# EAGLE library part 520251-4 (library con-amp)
AMP connector
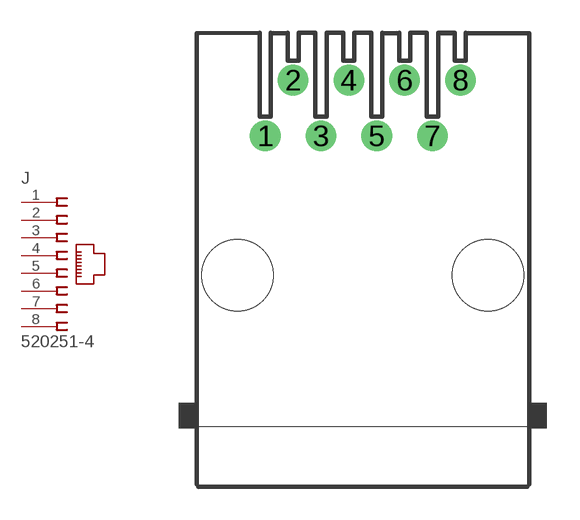
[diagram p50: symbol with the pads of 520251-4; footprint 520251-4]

Designator prefix J

## 520251-4 (MF: TYCO ELECTRONICS; MPN: 5520251-4; OC_FARNELL: 1557070; OC_NEWARK: 42K7223)  [520251-4]
1  1  pas
2  2  pas
3  3  pas
4  4  pas
5  5  pas
6  6  pas
7  7  pas
8  8  pas

## Footprint 520251-4 (pad centres in mm)
Modular Jack with Panel Stops
drill 0.889 round: 1 -4.445,6.35; 2 -3.175,8.89; 3 -1.905,6.35; 4 -0.635,8.89; 5 0.635,6.35; 6 1.905,8.89; 7 3.175,6.35; 8 4.445,8.89
hole 3.251 at -5.715,0
hole 3.251 at 5.715,0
